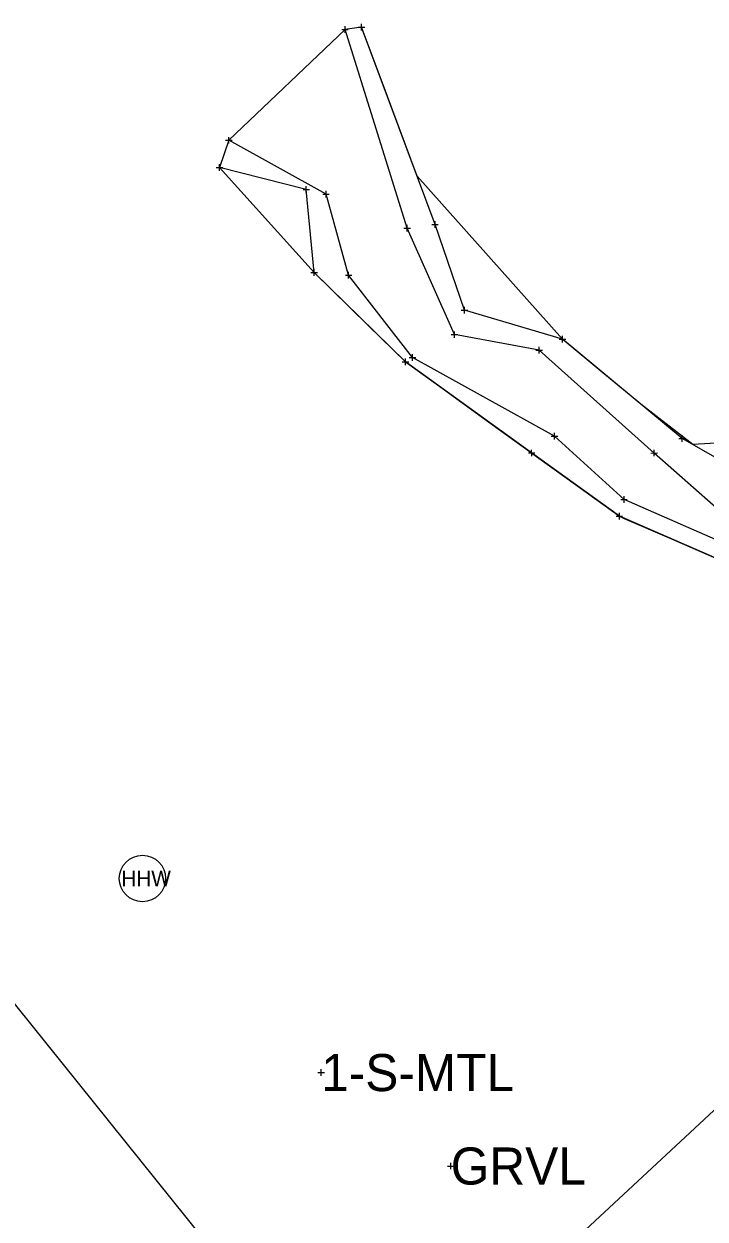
# Model space of a CAD drawing. Extents: x -1 to 1157254, y -1 to 2021979.
# Drawn here: x 1149227.6 to 1149359.7, y 2018913.3 to 2019145.3 of the extents above; entities that cross this region are included whole.
import ezdxf

# ---------------------------------------------------------------- set-up
doc = ezdxf.new("R2010")
doc.units = 0
for name, color, linetype in [('S_BUILDING_ANNOT', 7, 'Continuous'), ('S_CONTOUR_MINOR', 7, 'Continuous'), ('S_CTL_TABLE', 7, 'Continuous'), ('S_DRIVEWAY_ANNOT', 7, 'Continuous'), ('S_EDGE_BITUMINOUS_ANNOT', 7, 'Continuous'), ('S_FIBER_OPTIC_CABLE_ANNOT', 7, 'Continuous'), ('S_GAS_PUMP_ISLAND_ANNOT', 7, 'Continuous'), ('S_GATE', 7, 'Continuous')]:
    doc.layers.add(name, color=color, linetype=linetype)

msp = doc.modelspace()

# ---------------------------------------------------------------- linework, layer by layer
at = {"layer": 'S_BUILDING_ANNOT'}
for p, q in [((1149289.24, 2019144.23), (1149290.51, 2019144.23)), ((1149289.88, 2019143.59), (1149289.87, 2019144.86)), ((1149289.87, 2019144.23), (1149289.87, 2019144.23)), ((1149266.71, 2019122.7), (1149267.98, 2019122.7)), ((1149267.35, 2019122.07), (1149267.34, 2019123.34)), ((1149267.34, 2019122.7), (1149267.34, 2019122.7)), ((1149285.55, 2019112.23), (1149286.82, 2019112.23)), ((1149286.19, 2019111.59), (1149286.19, 2019112.86)), ((1149286.19, 2019112.23), (1149286.19, 2019112.23)), ((1149301.28, 2019105.65), (1149302.55, 2019105.65)), ((1149301.91, 2019105.01), (1149301.91, 2019106.29)), ((1149301.91, 2019105.65), (1149301.91, 2019105.65)), ((1149290.57, 2019095.89), (1149290.56, 2019097.17)), ((1149289.93, 2019096.53), (1149291.2, 2019096.53)), ((1149290.57, 2019096.53), (1149290.57, 2019096.53)), ((1149311.1, 2019084.34), (1149311.1, 2019085.61)), ((1149310.46, 2019084.97), (1149311.73, 2019084.98)), ((1149311.1, 2019084.98), (1149311.1, 2019084.98)), ((1149302.98, 2019079.9), (1149302.97, 2019081.17)), ((1149326.89, 2019081.97), (1149328.17, 2019081.98)), ((1149327.53, 2019081.34), (1149327.53, 2019082.61)), ((1149327.53, 2019081.98), (1149327.53, 2019081.98)), ((1149302.34, 2019080.53), (1149303.61, 2019080.54)), ((1149302.98, 2019080.53), (1149302.98, 2019080.53)), ((1149329.87, 2019065.25), (1149331.14, 2019065.25)), ((1149330.51, 2019064.61), (1149330.51, 2019065.88)), ((1149330.51, 2019065.25), (1149330.51, 2019065.25)), ((1149349.86, 2019061.36), (1149349.86, 2019062.63)), ((1149349.22, 2019061.99), (1149350.49, 2019062)), ((1149349.86, 2019061.99), (1149349.86, 2019061.99)), ((1149344.01, 2019052.32), (1149344.01, 2019053.6)), ((1149343.37, 2019052.96), (1149344.64, 2019052.96)), ((1149344.01, 2019052.96), (1149344.01, 2019052.96)), ((1149284.59, 2018941.71), (1149285.86, 2018941.71)), ((1149285.23, 2018941.07), (1149285.23, 2018942.35)), ((1149285.23, 2018941.71), (1149285.23, 2018941.71)), ((1149309.74, 2018923.57), (1149311.02, 2018923.57)), ((1149310.38, 2018922.93), (1149310.38, 2018924.21)), ((1149310.38, 2018923.57), (1149310.38, 2018923.57))]:
    msp.add_line(p, q, dxfattribs=at)
at = {"layer": 'S_CONTOUR_MINOR'}
for points in [[(1149450.85, 2019017.6), (1149294.1, 2018871.71)], [(1149292.61, 2018871.81), (1149177.53, 2019015.03)]]:
    msp.add_lwpolyline(points, dxfattribs=at)
at = {"layer": 'S_CTL_TABLE'}
for p, q in [((1149292.42, 2019144.66), (1149293.7, 2019144.66)), ((1149293.06, 2019144.03), (1149293.06, 2019145.3)), ((1149293.06, 2019144.66), (1149293.06, 2019144.66)), ((1149265.52, 2019116.79), (1149265.52, 2019118.06)), ((1149264.88, 2019117.42), (1149266.15, 2019117.42)), ((1149265.52, 2019117.42), (1149265.52, 2019117.42)), ((1149282.36, 2019112.54), (1149282.36, 2019113.81)), ((1149281.72, 2019113.17), (1149282.99, 2019113.18)), ((1149282.36, 2019113.17), (1149282.36, 2019113.17)), ((1149306.7, 2019106.38), (1149307.97, 2019106.38)), ((1149307.34, 2019105.74), (1149307.33, 2019107.01)), ((1149307.34, 2019106.38), (1149307.34, 2019106.38)), ((1149283.89, 2019096.39), (1149283.88, 2019097.66)), ((1149283.25, 2019097.02), (1149284.52, 2019097.02)), ((1149283.88, 2019097.02), (1149283.88, 2019097.02)), ((1149313.06, 2019089.07), (1149313.06, 2019090.34)), ((1149312.43, 2019089.71), (1149313.7, 2019089.71)), ((1149313.06, 2019089.71), (1149313.06, 2019089.71)), ((1149331.42, 2019084.08), (1149332.69, 2019084.08)), ((1149332.06, 2019083.45), (1149332.05, 2019084.72)), ((1149332.05, 2019084.08), (1149332.05, 2019084.08)), ((1149300.96, 2019079.71), (1149302.23, 2019079.71)), ((1149301.59, 2019079.07), (1149301.59, 2019080.34)), ((1149301.59, 2019079.71), (1149301.59, 2019079.71)), ((1149354.63, 2019064.82), (1149355.9, 2019064.82)), ((1149355.27, 2019064.19), (1149355.27, 2019065.46)), ((1149355.27, 2019064.82), (1149355.27, 2019064.82)), ((1149326.08, 2019061.36), (1149326.07, 2019062.64)), ((1149325.44, 2019062), (1149326.71, 2019062)), ((1149326.07, 2019062), (1149326.07, 2019062)), ((1149342.45, 2019049.72), (1149343.73, 2019049.73)), ((1149343.09, 2019049.09), (1149343.09, 2019050.36)), ((1149343.09, 2019049.73), (1149343.09, 2019049.73))]:
    msp.add_line(p, q, dxfattribs=at)
at = {"layer": 'S_DRIVEWAY_ANNOT'}
for points in [[(1149534.83, 2019055.5), (1149530.87, 2019056.39), (1149520.17, 2019054.91), (1149511.12, 2019055.68), (1149496.15, 2019053.32), (1149467.51, 2019049.09), (1149435.85, 2019042.86), (1149410.83, 2019043.89), (1149368.93, 2019045.14), (1149349.86, 2019061.99), (1149327.53, 2019081.98), (1149311.1, 2019084.98), (1149301.91, 2019105.65), (1149289.87, 2019144.23)], [(1149524.37, 2019043.27), (1149517.9, 2019045.37), (1149513.43, 2019045.1), (1149496.56, 2019043.9), (1149471.51, 2019038.15), (1149438.65, 2019033.94), (1149405.93, 2019035.32), (1149379.02, 2019037.66), (1149344.01, 2019052.96), (1149330.51, 2019065.25), (1149302.98, 2019080.53), (1149290.57, 2019096.53), (1149286.19, 2019112.23), (1149267.34, 2019122.7)]]:
    msp.add_lwpolyline(points, dxfattribs=at)
at = {"layer": 'S_EDGE_BITUMINOUS_ANNOT'}
for points in [[(1149531.03, 2019069.65), (1149522.21, 2019060.77), (1149518.93, 2019058.63), (1149511.36, 2019059.55), (1149495.33, 2019056.85), (1149466.74, 2019054.88), (1149435.79, 2019046.85), (1149411.94, 2019047.8), (1149374.71, 2019053.77), (1149355.27, 2019064.82), (1149332.05, 2019084.08), (1149313.06, 2019089.71), (1149307.34, 2019106.38), (1149293.06, 2019144.66)], [(1149470.95, 2019015.88), (1149480.9, 2019023.42), (1149490.47, 2019031.18), (1149495.83, 2019040.44), (1149472.33, 2019030.55), (1149438.25, 2019027.17), (1149405.64, 2019028.8), (1149380.72, 2019033.36), (1149343.09, 2019049.73), (1149326.07, 2019062), (1149301.59, 2019079.71), (1149283.88, 2019097.02), (1149282.36, 2019113.17), (1149265.52, 2019117.42)]]:
    msp.add_lwpolyline(points, dxfattribs=at)
at = {"layer": 'S_FIBER_OPTIC_CABLE_ANNOT'}
msp.add_circle((1149250.57, 2018979.39), 4.5, dxfattribs=at)
at = {"layer": 'S_GAS_PUMP_ISLAND_ANNOT'}
msp.add_lwpolyline([(1149406.8, 2019066.5), (1149357.35, 2019063.64), (1149347.58, 2019071.2), (1149339.89, 2019077.59), (1149332.19, 2019083.97), (1149332.05, 2019084.08), (1149303.84, 2019115.75), (1149300.35, 2019125.11), (1149296.86, 2019134.48), (1149293.36, 2019143.85), (1149293.06, 2019144.66), (1149289.87, 2019144.23), (1149267.34, 2019122.7), (1149265.52, 2019117.42), (1149283.88, 2019097.02), (1149287.3, 2019093.68), (1149294.45, 2019086.7), (1149301.59, 2019079.71), (1149301.8, 2019079.56), (1149309.89, 2019073.71), (1149317.98, 2019067.85), (1149326.07, 2019062), (1149326.99, 2019061.34), (1149335.04, 2019055.53), (1149343.09, 2019049.73), (1149344.05, 2019049.31), (1149353.22, 2019045.32), (1149362.38, 2019041.34)], dxfattribs=at)

# ---------------------------------------------------------------- texts
at = {"layer": 'S_FIBER_OPTIC_CABLE_ANNOT'}
msp.add_text('HHW', height=2.999, dxfattribs=at).set_placement((1149246.49, 2018977.89))
at = {"layer": 'S_GATE'}
for s, p in [('1-S-MTL', (1149285.23, 2018938.11)), ('GRVL', (1149310.38, 2018919.97))]:
    msp.add_text(s, height=7.2, dxfattribs=at).set_placement(p)

doc.saveas('drawing.dxf')
